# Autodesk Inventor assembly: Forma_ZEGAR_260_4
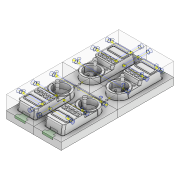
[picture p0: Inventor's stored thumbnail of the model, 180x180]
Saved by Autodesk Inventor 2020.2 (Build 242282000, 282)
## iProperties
Created: 2015-01
Part Number: Forma_ZEGAR_260_4
Document SubType Name: Assembly
Designer: F.Stasiak
Catalog Web Link: www.expertbooks.pl
Manager: www.cadconsulting.pl
Company: Fabian Stasiak CAD Consulting
Author: F.Stasiak
Subject: Zbiór ćwiczeń. Autodesk Inventor 2020. Kurs Professional
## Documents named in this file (4)
- C:\2020_Kurs_Professional\R6 Formy\Forma_ZEGAR_260_4.iam
- C:\2020_Kurs_Professional\R6 Formy\Komponenty\Forma_ZEGAR_260_4_ZEGAR_260_LY.iam
- C:\2020_Kurs_Professional\R6 Formy\Komponenty\Forma_ZEGAR_260_4_RG.ipt
- C:\2020_Kurs_Professional\R6 Formy\Komponenty\Forma_ZEGAR_260_4_CH.ipt
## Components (3 placed, 3 different names)
1. Forma_ZEGAR_260_4_ZEGAR_260_LY:1 [sub-assembly] — Równoległy:1, Równoległy:2, Równoległy:3
2. Forma_ZEGAR_260_4_RG:1 — Równoległy:4, Równoległy:5, Równoległy:6
3. Forma_ZEGAR_260_4_CH:1
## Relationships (6: Flush 6)
- Równoległy:1 [Flush]: Forma_ZEGAR_260_4_ZEGAR_260_LY:1
- Równoległy:2 [Flush]: Forma_ZEGAR_260_4_ZEGAR_260_LY:1
- Równoległy:3 [Flush]: Forma_ZEGAR_260_4_ZEGAR_260_LY:1
- Równoległy:4 [Flush]: Forma_ZEGAR_260_4_RG:1
- Równoległy:5 [Flush]: Forma_ZEGAR_260_4_RG:1
- Równoległy:6 [Flush]: Forma_ZEGAR_260_4_RG:1
